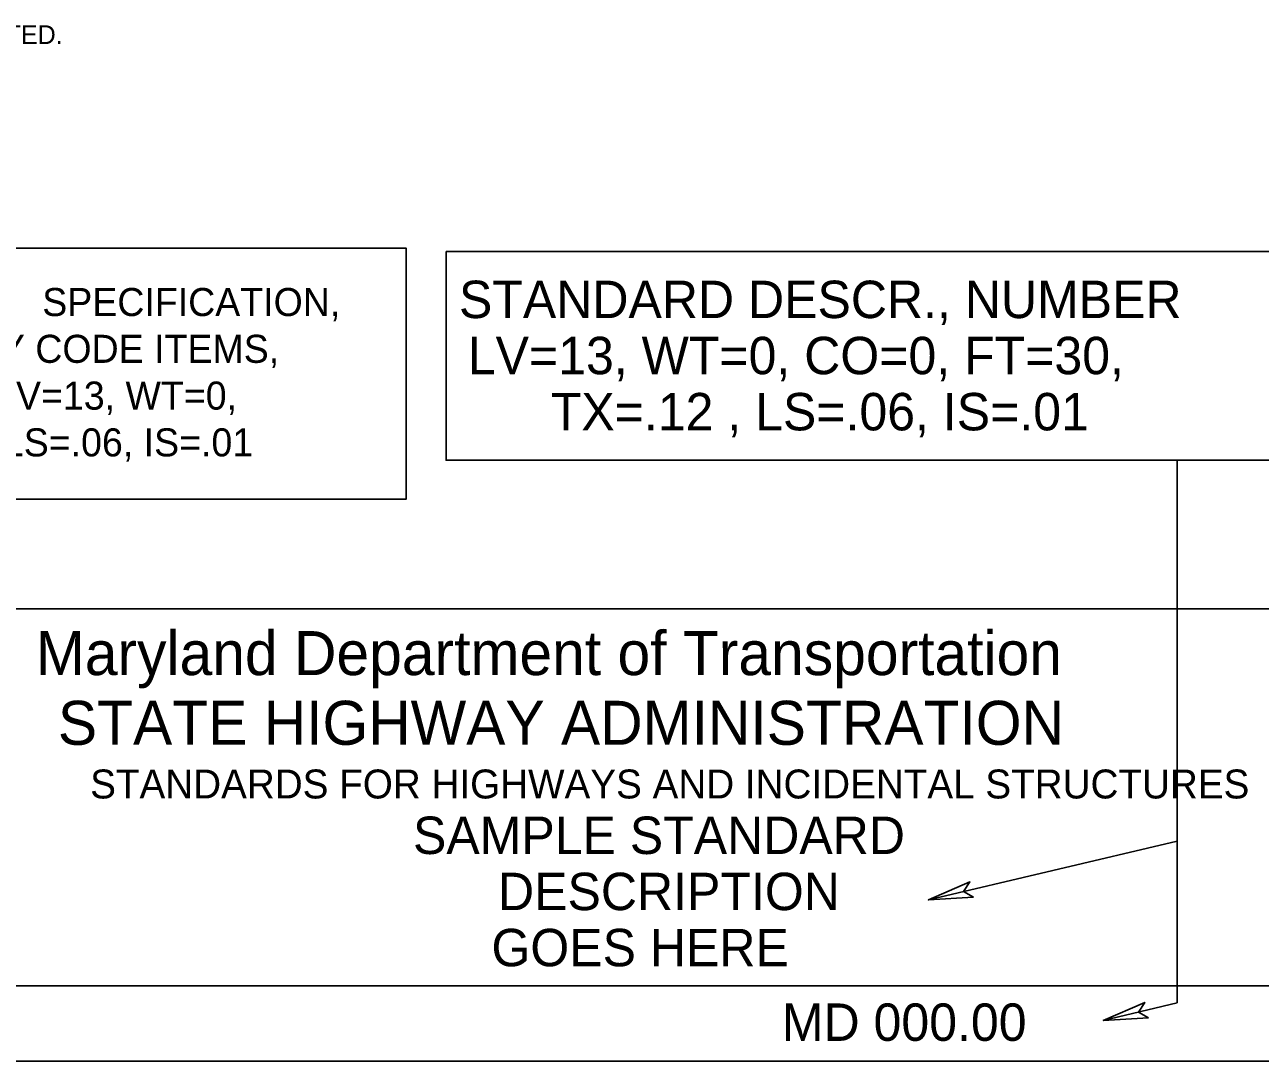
# Model space of a CAD drawing. Extents: x -0.5 to 21.6, y 4.3 to 17.8.
# Drawn here: x 3.481 to 7.445, y 5.937 to 9.261 of the extents above; entities that cross this region are included whole.
import ezdxf

# ---------------------------------------------------------------- set-up
doc = ezdxf.new("R2010")
doc.units = 0
for name, color, linetype in [('DETL-DIMS', 7, 'Continuous'), ('DETL-LINE', 7, 'Continuous'), ('DETL-NOTE', 7, 'Continuous'), ('TTLB-TEXT', 7, 'Continuous'), ('USER-BORD', 7, 'Continuous')]:
    doc.layers.add(name, color=color, linetype=linetype)

msp = doc.modelspace()

# ---------------------------------------------------------------- linework, layer by layer
at = {"layer": 'DETL-DIMS'}
for p, q in [((7.1787, 7.8648), (7.1787, 6.1246)), ((7.1787, 6.6431), (6.3803, 6.4551)), ((6.3803, 6.4551), (6.5137, 6.5124)), ((6.4932, 6.4817), (6.5137, 6.5124)), ((6.3803, 6.4551), (6.5253, 6.4633)), ((6.5253, 6.4633), (6.4932, 6.4817)), ((6.9411, 6.0687), (7.0745, 6.126)), ((7.1787, 6.1246), (6.9411, 6.0687)), ((7.054, 6.0953), (7.0745, 6.126)), ((6.9411, 6.0687), (7.0861, 6.0769)), ((7.0861, 6.0769), (7.054, 6.0953))]:
    msp.add_line(p, q, dxfattribs=at)
for points in [[(6.5253, 6.4633), (6.3803, 6.4551), (6.5137, 6.5124), (6.4932, 6.4817)], [(7.0861, 6.0769), (6.9411, 6.0687), (7.0745, 6.126), (7.054, 6.0953)]]:
    msp.add_lwpolyline(points, close=True, dxfattribs=at)
at = {"layer": 'DETL-LINE'}
msp.add_lwpolyline([(0.3943, 14.1527), (0.3943, 16.2906), (7.7685, 16.2906), (7.7685, 5.9375), (0.3943, 5.9375), (0.3943, 13.6862)], dxfattribs=at)
at = {"layer": 'TTLB-TEXT'}
for p, q in [((7.7685, 7.3883), (0.3943, 7.3883)), ((3.2956, 6.1793), (7.7685, 6.1793)), ((7.7685, 5.9375), (0.3943, 5.9375))]:
    msp.add_line(p, q, dxfattribs=at)
for points in [[(0.3943, 16.2906), (7.7685, 16.2906), (7.7685, 5.9375), (0.3943, 5.9375)], [(2.4865, 8.5442), (4.7055, 8.5442), (4.7055, 7.74), (2.4865, 7.74)], [(4.8334, 8.534), (7.5921, 8.534), (7.5921, 7.8648), (4.8334, 7.8648)]]:
    msp.add_lwpolyline(points, close=True, dxfattribs=at)
at = {"layer": 'USER-BORD'}
for p, q in [((7.7685, 7.3883), (0.3943, 7.3883)), ((3.2956, 6.1793), (7.7685, 6.1793)), ((6.4001, 6.0629), (6.4001, 6.0629)), ((7.7685, 5.9375), (0.3943, 5.9375))]:
    msp.add_line(p, q, dxfattribs=at)

# ---------------------------------------------------------------- texts
at = {"layer": 'DETL-NOTE'}
for s, height, p in [('1. THIS IS WHERE THE GENERAL NOTES ARE LOCATED.', 0.06, (1.4142, 9.1994)), ('STANDARDS FOR HIGHWAYS AND INCIDENTAL STRUCTURES', 0.09269, (3.6914, 6.7803))]:
    msp.add_text(s, height=height, dxfattribs=at).set_placement(p)
at = {"layer": 'TTLB-TEXT'}
for s, height, p in [('SPECIFICATION,', 0.09, (3.5376, 8.327)), ('STANDARD DESCR., NUMBER  ', 0.12, (4.8745, 8.3205)), (' CATEGORY CODE ITEMS, ', 0.09, (2.7731, 8.177)), ('LV=13, WT=0, CO=0, FT=30, ', 0.12, (4.9028, 8.1405)), ('FT=30, TX=.09, LV=13, WT=0,', 0.09, (2.5102, 8.027)), ('TX=.12 , LS=.06, IS=.01', 0.12, (5.169, 7.9605)), (' CO=0, LS=.06, IS=.01', 0.09, (2.9933, 7.877)), ('Maryland Department of Transportation', 0.14105, (3.517, 7.1757)), ('STATE HIGHWAY ADMINISTRATION', 0.14105, (3.5878, 6.9522)), ('STANDARDS FOR HIGHWAYS AND INCIDENTAL STRUCTURES', 0.09269, (3.6913, 6.7802)), ('SAMPLE STANDARD', 0.12, (4.727, 6.6021)), ('DESCRIPTION', 0.12, (4.9998, 6.4221)), ('GOES HERE  ', 0.12, (4.9786, 6.2421)), ('MD 000.00', 0.12, (5.9104, 6.0029))]:
    msp.add_text(s, height=height, dxfattribs=at).set_placement(p)
at = {"layer": 'USER-BORD'}
for s, p in [('Maryland Department of Transportation', (3.5171, 7.1758)), ('STATE HIGHWAY ADMINISTRATION', (3.5879, 6.9523))]:
    msp.add_text(s, height=0.14105, dxfattribs=at).set_placement(p)

doc.saveas('drawing.dxf')
